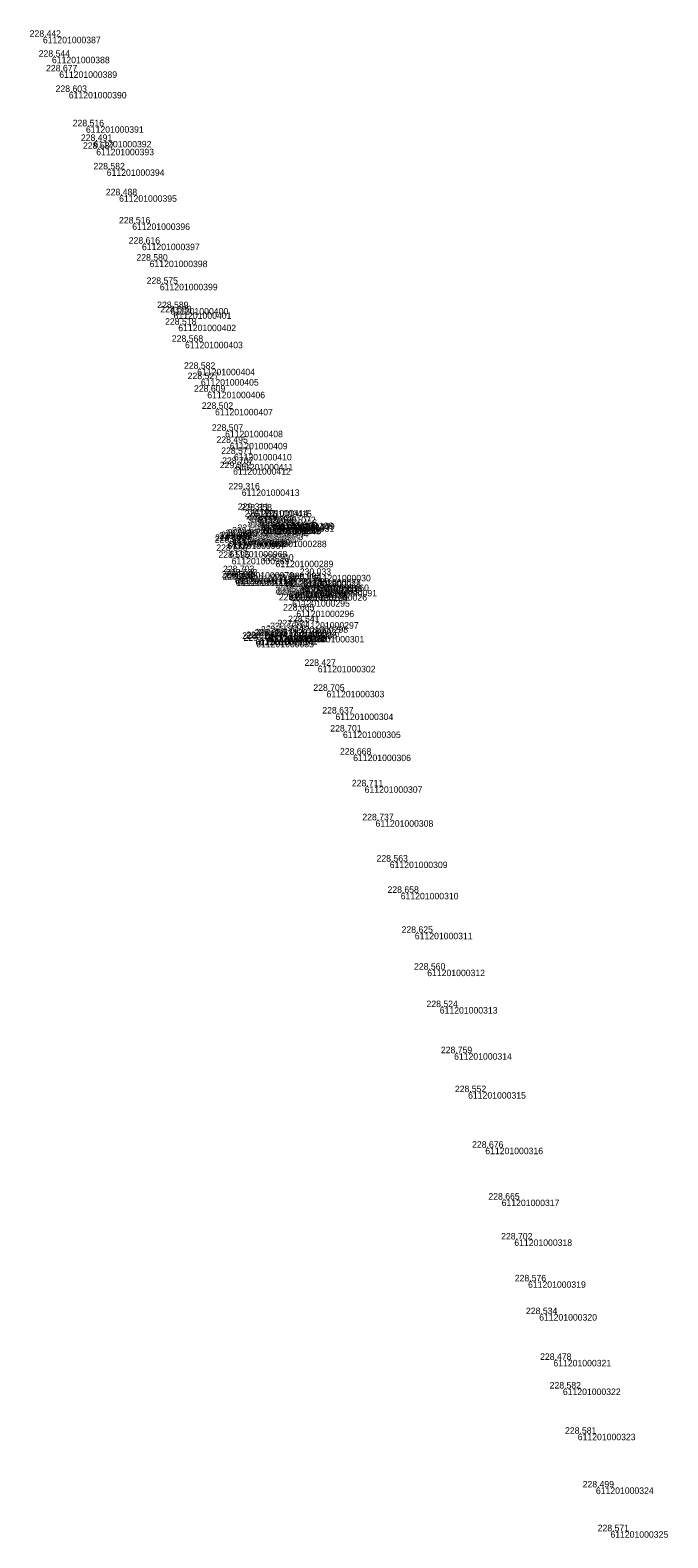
# Model space of a CAD drawing. Extents: x -771040 to -768909, y -1052366 to -1050115.
# Drawn here: x -769188.7 to -769070.5, y -1051235.2 to -1050956 of the extents above; entities that cross this region are included whole.
import ezdxf

# ---------------------------------------------------------------- set-up
doc = ezdxf.new("R2010")
doc.units = 0
doc.layers.add('Vrstva 60', color=7, linetype='Continuous')
doc.layers.add('Vrstva 61', color=7, linetype='Continuous')

msp = doc.modelspace()

# ---------------------------------------------------------------- linework, layer by layer
at = {"layer": 'Vrstva 60'}
for p, q in [((-769186.35, -1050957.25), (-769186.35, -1050957.25)), ((-769184.68, -1050960.95), (-769184.68, -1050960.95)), ((-769183.32, -1050963.66), (-769183.32, -1050963.66)), ((-769181.55, -1050967.47), (-769181.55, -1050967.47)), ((-769178.38, -1050973.83), (-769178.38, -1050973.83)), ((-769176.95, -1050976.54), (-769176.95, -1050976.54)), ((-769176.47, -1050978), (-769176.47, -1050978)), ((-769174.52, -1050981.81), (-769174.52, -1050981.81)), ((-769172.23, -1050986.61), (-769172.23, -1050986.61)), ((-769169.8, -1050991.82), (-769169.8, -1050991.82)), ((-769168, -1050995.57), (-769168, -1050995.57)), ((-769166.57, -1050998.71), (-769166.57, -1050998.71)), ((-769164.68, -1051003), (-769164.68, -1051003)), ((-769162.72, -1051007.49), (-769162.72, -1051007.49)), ((-769162.13, -1051008.29), (-769162.13, -1051008.29)), ((-769161.26, -1051010.57), (-769161.26, -1051010.57)), ((-769160.01, -1051013.74), (-769160.01, -1051013.74)), ((-769157.76, -1051018.74), (-769157.76, -1051018.74)), ((-769157.07, -1051020.65), (-769157.07, -1051020.65)), ((-769155.89, -1051022.99), (-769155.89, -1051022.99)), ((-769154.45, -1051026.16), (-769154.45, -1051026.16)), ((-769152.59, -1051030.22), (-769152.59, -1051030.22)), ((-769151.72, -1051032.46), (-769151.72, -1051032.46)), ((-769150.95, -1051034.51), (-769150.95, -1051034.51)), ((-769150.68, -1051036.35), (-769150.68, -1051036.35)), ((-769151.11, -1051037.14), (-769151.11, -1051037.14)), ((-769149.5, -1051041.08), (-769149.5, -1051041.08)), ((-769147.88, -1051044.87), (-769147.88, -1051044.87)), ((-769147.24, -1051044.98), (-769147.24, -1051044.98)), ((-769146.52, -1051046.12), (-769146.52, -1051046.12)), ((-769146.24, -1051046.63), (-769146.24, -1051046.63)), ((-769145.98, -1051047.32), (-769145.98, -1051047.32)), ((-769145.98, -1051048), (-769145.98, -1051048)), ((-769145.81, -1051047.64), (-769145.81, -1051047.64)), ((-769145.58, -1051048.1), (-769145.58, -1051048.1)), ((-769145.57, -1051048.21), (-769145.57, -1051048.21)), ((-769145.42, -1051048.12), (-769145.42, -1051048.12)), ((-769143.87, -1051047.48), (-769143.87, -1051047.48)), ((-769143.26, -1051047.22), (-769143.26, -1051047.22)), ((-769143.07, -1051047.72), (-769143.07, -1051047.72)), ((-769142.99, -1051047.33), (-769142.99, -1051047.33)), ((-769152.15, -1051050.93), (-769152.15, -1051050.93)), ((-769152, -1051050.61), (-769152, -1051050.61)), ((-769151.26, -1051050.22), (-769151.26, -1051050.22)), ((-769151.25, -1051050.28), (-769151.25, -1051050.28)), ((-769150.9, -1051050.08), (-769150.9, -1051050.08)), ((-769150.07, -1051049.75), (-769150.07, -1051049.75)), ((-769149.65, -1051049.66), (-769149.65, -1051049.66)), ((-769148.84, -1051049.23), (-769148.84, -1051049.23)), ((-769147.83, -1051048.78), (-769147.83, -1051048.78)), ((-769144.47, -1051050.57), (-769144.47, -1051050.57)), ((-769151.77, -1051052.47), (-769151.77, -1051052.47)), ((-769151.37, -1051053.76), (-769151.37, -1051053.76)), ((-769150.53, -1051056.4), (-769150.53, -1051056.4)), ((-769143.24, -1051054.28), (-769143.24, -1051054.28)), ((-769150.76, -1051057.41), (-769150.76, -1051057.41)), ((-769150.61, -1051057.78), (-769150.61, -1051057.78)), ((-769150.3, -1051057.73), (-769150.3, -1051057.73)), ((-769149.96, -1051057.01), (-769149.96, -1051057.01)), ((-769141.65, -1051057.9), (-769141.65, -1051057.9)), ((-769138.75, -1051059.25), (-769138.75, -1051059.25)), ((-769138.35, -1051059.02), (-769138.35, -1051059.02)), ((-769138.15, -1051057.68), (-769138.15, -1051057.68)), ((-769138.14, -1051058.1), (-769138.14, -1051058.1)), ((-769137.83, -1051058.85), (-769137.83, -1051058.85)), ((-769136.65, -1051058.69), (-769136.65, -1051058.69)), ((-769136.3, -1051056.9), (-769136.3, -1051056.9)), ((-769140.85, -1051060.32), (-769140.85, -1051060.32)), ((-769140.76, -1051059.95), (-769140.76, -1051059.95)), ((-769140.58, -1051060.54), (-769140.58, -1051060.54)), ((-769140.36, -1051059.95), (-769140.36, -1051059.95)), ((-769140.18, -1051061.6), (-769140.18, -1051061.6)), ((-769136.99, -1051060.47), (-769136.99, -1051060.47)), ((-769135.15, -1051059.69), (-769135.15, -1051059.69)), ((-769139.39, -1051063.52), (-769139.39, -1051063.52)), ((-769143.5, -1051067.6), (-769143.5, -1051067.6)), ((-769142.56, -1051067.46), (-769142.56, -1051067.46)), ((-769141.8, -1051066.94), (-769141.8, -1051066.94)), ((-769140.5, -1051066.43), (-769140.5, -1051066.43)), ((-769138.55, -1051065.66), (-769138.55, -1051065.66)), ((-769146.96, -1051068.75), (-769146.96, -1051068.75)), ((-769146.83, -1051069.12), (-769146.83, -1051069.12)), ((-769146.21, -1051068.6), (-769146.21, -1051068.6)), ((-769144.69, -1051068.19), (-769144.69, -1051068.19)), ((-769144.68, -1051068.15), (-769144.68, -1051068.15)), ((-769144.54, -1051068.1), (-769144.54, -1051068.1)), ((-769144.33, -1051068.15), (-769144.33, -1051068.15)), ((-769137.5, -1051068.22), (-769137.5, -1051068.22)), ((-769135.42, -1051073.75), (-769135.42, -1051073.75)), ((-769133.79, -1051078.38), (-769133.79, -1051078.38)), ((-769132.13, -1051082.58), (-769132.13, -1051082.58)), ((-769130.75, -1051085.91), (-769130.75, -1051085.91)), ((-769128.85, -1051090.19), (-769128.85, -1051090.19)), ((-769126.73, -1051096.06), (-769126.73, -1051096.06)), ((-769124.71, -1051102.34), (-769124.71, -1051102.34)), ((-769122.07, -1051110), (-769122.07, -1051110)), ((-769120.04, -1051115.79), (-769120.04, -1051115.79)), ((-769117.43, -1051123.18), (-769117.43, -1051123.18)), ((-769115.13, -1051130.01), (-769115.13, -1051130.01)), ((-769112.81, -1051136.94), (-769112.81, -1051136.94)), ((-769110.15, -1051145.48), (-769110.15, -1051145.48)), ((-769107.55, -1051152.69), (-769107.55, -1051152.69)), ((-769104.37, -1051162.98), (-769104.37, -1051162.98)), ((-769101.34, -1051172.59), (-769101.34, -1051172.59)), ((-769098.99, -1051179.97), (-769098.99, -1051179.97)), ((-769096.45, -1051187.73), (-769096.45, -1051187.73)), ((-769094.38, -1051193.8), (-769094.38, -1051193.8)), ((-769091.75, -1051202.27), (-769091.75, -1051202.27)), ((-769089.99, -1051207.58), (-769089.99, -1051207.58)), ((-769087.23, -1051215.95), (-769087.23, -1051215.95)), ((-769083.87, -1051225.89), (-769083.87, -1051225.89)), ((-769081.18, -1051234.01), (-769081.18, -1051234.01))]:
    msp.add_line(p, q, dxfattribs=at)

# ---------------------------------------------------------------- texts
for s, p in [('611201000387', (-769186.35, -1050958.45)), ('611201000388', (-769184.68, -1050962.15)), ('611201000389', (-769183.32, -1050964.86)), ('611201000390', (-769181.55, -1050968.67)), ('611201000391', (-769178.38, -1050975.03)), ('611201000392', (-769176.95, -1050977.74)), ('611201000393', (-769176.47, -1050979.2)), ('611201000394', (-769174.52, -1050983.01)), ('611201000395', (-769172.23, -1050987.81)), ('611201000396', (-769169.8, -1050993.02)), ('611201000397', (-769168, -1050996.77)), ('611201000398', (-769166.57, -1050999.91)), ('611201000399', (-769164.68, -1051004.2)), ('611201000400', (-769162.72, -1051008.69)), ('611201000401', (-769162.13, -1051009.49)), ('611201000402', (-769161.26, -1051011.77)), ('611201000403', (-769160.01, -1051014.94)), ('611201000404', (-769157.76, -1051019.94)), ('611201000405', (-769157.07, -1051021.85)), ('611201000406', (-769155.89, -1051024.19)), ('611201000407', (-769154.45, -1051027.36)), ('611201000408', (-769152.59, -1051031.42)), ('611201000409', (-769151.72, -1051033.66)), ('611201000410', (-769150.95, -1051035.71)), ('611201000411', (-769150.68, -1051037.55)), ('611201000412', (-769151.11, -1051038.34)), ('611201000413', (-769149.5, -1051042.28)), ('611201000414', (-769147.88, -1051046.07)), ('611201000415', (-769147.24, -1051046.18)), ('611201001072', (-769146.52, -1051047.32)), ('611201000416', (-769146.24, -1051047.83)), ('611201000963', (-769145.98, -1051049.2)), ('611201000973', (-769145.98, -1051048.52)), ('611201000417', (-769145.81, -1051048.84)), ('611201000287', (-769145.58, -1051049.3)), ('611201001043', (-769145.57, -1051049.41)), ('611201001106', (-769145.42, -1051049.32)), ('611201001107', (-769143.87, -1051048.68)), ('611201001108', (-769143.26, -1051048.42)), ('611201000031', (-769143.07, -1051048.92)), ('611201001109', (-769142.99, -1051048.53)), ('611201000967', (-769152.15, -1051052.12)), ('611201000966', (-769152, -1051051.81)), ('611201000041', (-769151.26, -1051051.42)), ('611201001110', (-769151.25, -1051051.48)), ('611201000040', (-769150.9, -1051051.28)), ('611201000965', (-769150.07, -1051050.95)), ('611201000039', (-769149.65, -1051050.86)), ('611201000038', (-769148.84, -1051050.43)), ('611201000964', (-769147.83, -1051049.98)), ('611201000288', (-769144.47, -1051051.77)), ('611201000968', (-769151.77, -1051053.67)), ('611201000969', (-769151.37, -1051054.96)), ('611201000970', (-769150.53, -1051057.6)), ('611201000289', (-769143.24, -1051055.48)), ('611201001112', (-769150.76, -1051058.61)), ('611201001113', (-769150.61, -1051058.98)), ('611201000032', (-769150.3, -1051058.93)), ('611201001111', (-769149.96, -1051058.21)), ('611201000290', (-769141.65, -1051059.1)), ('611201000293', (-769138.75, -1051060.45)), ('611201001115', (-769138.35, -1051060.22)), ('611201000027', (-769138.15, -1051058.88)), ('611201000028', (-769138.14, -1051059.3)), ('611201001116', (-769137.83, -1051060.05)), ('611201001160', (-769136.65, -1051059.89)), ('611201000030', (-769136.3, -1051058.1)), ('611201001073', (-769140.85, -1051061.52)), ('611201000291', (-769140.76, -1051061.15)), ('611201000294', (-769140.58, -1051061.74)), ('611201000292', (-769140.36, -1051061.15)), ('611201000295', (-769140.18, -1051062.8)), ('611201000026', (-769136.99, -1051061.67)), ('611201000091', (-769135.15, -1051060.89)), ('611201000296', (-769139.39, -1051064.72)), ('611201000299', (-769143.5, -1051068.8)), ('611201000036', (-769142.56, -1051068.66)), ('611201000037', (-769141.8, -1051068.14)), ('611201000298', (-769140.5, -1051067.63)), ('611201000297', (-769138.55, -1051066.86)), ('611201001114', (-769146.96, -1051069.95)), ('611201000033', (-769146.83, -1051070.32)), ('611201000971', (-769146.21, -1051069.8)), ('611201000972', (-769144.68, -1051069.35)), ('611201000034', (-769144.69, -1051069.39)), ('611201000300', (-769144.54, -1051069.3)), ('611201000035', (-769144.33, -1051069.35)), ('611201000301', (-769137.5, -1051069.42)), ('611201000302', (-769135.42, -1051074.95)), ('611201000303', (-769133.79, -1051079.58)), ('611201000304', (-769132.13, -1051083.78)), ('611201000305', (-769130.75, -1051087.11)), ('611201000306', (-769128.85, -1051091.39)), ('611201000307', (-769126.73, -1051097.26)), ('611201000308', (-769124.71, -1051103.54)), ('611201000309', (-769122.07, -1051111.2)), ('611201000310', (-769120.04, -1051116.99)), ('611201000311', (-769117.43, -1051124.38)), ('611201000312', (-769115.13, -1051131.21)), ('611201000313', (-769112.81, -1051138.14)), ('611201000314', (-769110.15, -1051146.68)), ('611201000315', (-769107.55, -1051153.89)), ('611201000316', (-769104.37, -1051164.18)), ('611201000317', (-769101.34, -1051173.79)), ('611201000318', (-769098.99, -1051181.17)), ('611201000319', (-769096.45, -1051188.93)), ('611201000320', (-769094.38, -1051195)), ('611201000321', (-769091.75, -1051203.47)), ('611201000322', (-769089.99, -1051208.78)), ('611201000323', (-769087.23, -1051217.15)), ('611201000324', (-769083.87, -1051227.09)), ('611201000325', (-769081.18, -1051235.21))]:
    msp.add_text(s, height=1.2, dxfattribs=at).set_placement(p)
at = {"layer": 'Vrstva 61'}
for s, p in [('228.442', (-769188.8, -1050957.25)), ('228.544', (-769187.13, -1050960.95)), ('228.677', (-769185.77, -1050963.66)), ('228.603', (-769184, -1050967.47)), ('228.516', (-769180.83, -1050973.83)), ('228.491', (-769179.31, -1050976.54)), ('228.537', (-769178.92, -1050978)), ('228.582', (-769176.97, -1050981.81)), ('228.488', (-769174.69, -1050986.61)), ('228.516', (-769172.25, -1050991.82)), ('228.616', (-769170.45, -1050995.57)), ('228.580', (-769169.02, -1050998.71)), ('228.575', (-769167.13, -1051003)), ('228.589', (-769165.18, -1051007.49)), ('228.588', (-769164.59, -1051008.29)), ('228.518', (-769163.71, -1051010.57)), ('228.568', (-769162.46, -1051013.74)), ('228.582', (-769160.21, -1051018.74)), ('228.527', (-769159.53, -1051020.65)), ('228.609', (-769158.35, -1051022.99)), ('228.502', (-769156.9, -1051026.16)), ('228.507', (-769155.04, -1051030.22)), ('228.495', (-769154.18, -1051032.46)), ('228.571', (-769153.31, -1051034.51)), ('229.342', (-769153.56, -1051037.14)), ('228.707', (-769153.14, -1051036.35)), ('229.316', (-769151.96, -1051041.08)), ('229.311', (-769150.24, -1051044.87)), ('228.358', (-769149.7, -1051044.98)), ('228.262', (-769148.97, -1051046.12)), ('228.318', (-769148.69, -1051046.63)), ('229.646', (-769151.29, -1051049.23)), ('227.918', (-769150.29, -1051048.78)), ('228.605', (-769148.43, -1051047.32)), ('228.601', (-769148.34, -1051048)), ('228.446', (-769148.26, -1051047.64)), ('228.470', (-769148.03, -1051048.1)), ('228.579', (-769148.02, -1051048.21)), ('228.473', (-769147.87, -1051048.12)), ('228.923', (-769146.32, -1051047.48)), ('229.294', (-769145.71, -1051047.22)), ('229.492', (-769145.44, -1051047.33)), ('229.861', (-769145.43, -1051047.72)), ('228.521', (-769154.51, -1051050.93)), ('228.503', (-769154.45, -1051050.61)), ('229.684', (-769153.71, -1051050.22)), ('228.303', (-769153.7, -1051050.28)), ('229.392', (-769153.35, -1051050.08)), ('227.985', (-769152.52, -1051049.75)), ('229.467', (-769152.1, -1051049.66)), ('228.628', (-769146.93, -1051050.57)), ('228.556', (-769154.22, -1051052.47)), ('228.595', (-769153.83, -1051053.76)), ('228.500', (-769145.69, -1051054.28)), ('228.505', (-769153.21, -1051057.41)), ('228.706', (-769153.07, -1051057.78)), ('228.703', (-769152.98, -1051056.4)), ('229.249', (-769152.75, -1051057.73)), ('228.533', (-769152.41, -1051057.01)), ('229.993', (-769140.6, -1051057.68)), ('230.033', (-769138.75, -1051056.9)), ('228.624', (-769144.1, -1051057.9)), ('228.879', (-769143.3, -1051060.32)), ('228.659', (-769143.21, -1051059.95)), ('228.716', (-769143.03, -1051060.54)), ('228.741', (-769142.71, -1051059.95)), ('228.823', (-769141.2, -1051059.25)), ('229.002', (-769140.8, -1051059.02)), ('229.895', (-769140.6, -1051058.1)), ('228.956', (-769140.28, -1051058.85)), ('230.022', (-769139.44, -1051060.47)), ('230.028', (-769139.1, -1051058.69)), ('230.062', (-769137.6, -1051059.69)), ('228.806', (-769142.63, -1051061.6)), ('228.665', (-769141.85, -1051063.52)), ('228.541', (-769140.91, -1051065.66)), ('228.624', (-769149.42, -1051068.75)), ('228.790', (-769148.67, -1051068.6)), ('228.686', (-769147.13, -1051068.15)), ('229.491', (-769147.04, -1051068.19)), ('228.370', (-769146.99, -1051068.1)), ('229.363', (-769146.78, -1051068.15)), ('227.497', (-769145.96, -1051067.6)), ('229.453', (-769145.01, -1051067.46)), ('229.608', (-769144.25, -1051066.94)), ('227.521', (-769142.86, -1051066.43)), ('228.492', (-769139.95, -1051068.22)), ('229.151', (-769149.18, -1051069.12)), ('228.427', (-769137.87, -1051073.75)), ('228.705', (-769136.24, -1051078.38)), ('228.637', (-769134.58, -1051082.58)), ('228.701', (-769133.1, -1051085.91)), ('228.668', (-769131.3, -1051090.19)), ('228.711', (-769129.09, -1051096.06)), ('228.737', (-769127.16, -1051102.34)), ('228.563', (-769124.52, -1051110)), ('228.658', (-769122.49, -1051115.79)), ('228.625', (-769119.88, -1051123.18)), ('228.560', (-769117.58, -1051130.01)), ('228.524', (-769115.26, -1051136.94)), ('228.759', (-769112.6, -1051145.48)), ('228.552', (-769110, -1051152.69)), ('228.676', (-769106.82, -1051162.98)), ('228.665', (-769103.8, -1051172.59)), ('228.702', (-769101.44, -1051179.97)), ('228.576', (-769098.9, -1051187.73)), ('228.534', (-769096.83, -1051193.8)), ('228.478', (-769094.21, -1051202.27)), ('228.582', (-769092.44, -1051207.58)), ('228.581', (-769089.59, -1051215.95)), ('228.499', (-769086.32, -1051225.89)), ('228.571', (-769083.54, -1051234.01))]:
    msp.add_text(s, height=1.2, dxfattribs=at).set_placement(p)

doc.saveas('drawing.dxf')
